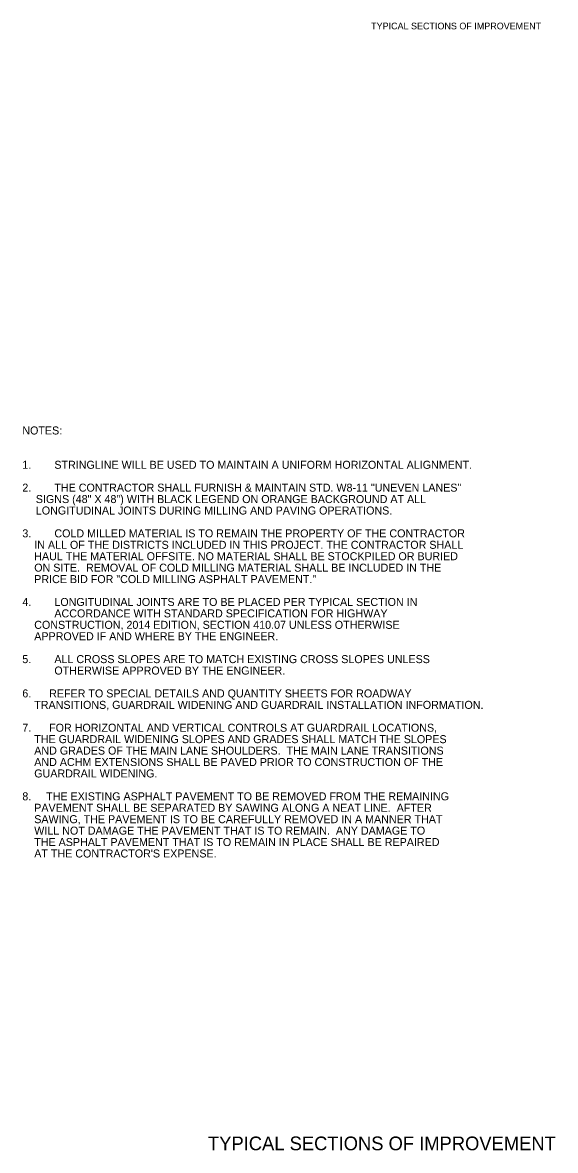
# Model space of a CAD drawing. Extents: x 544259 to 1930787, y -1961343 to 596640.
# Drawn here: x 545302 to 545768, y -1949643 to -1948656 of the extents above; entities that cross this region are included whole.
import ezdxf

# ---------------------------------------------------------------- set-up
doc = ezdxf.new("R2010")
doc.units = 0
for name, color, linetype in [('R_Border', 7, 'Continuous'), ('R_Border Notes', 7, 'Continuous'), ('R_Border Prem', 7, 'Continuous')]:
    doc.layers.add(name, color=color, linetype=linetype)

msp = doc.modelspace()

# ---------------------------------------------------------------- texts
at = {"layer": 'R_Border'}
msp.add_text('TYPICAL SECTIONS OF IMPROVEMENT', height=12, rotation=360, dxfattribs=at).set_placement((545464.19, -1949642.82))
at = {"layer": 'R_Border Notes'}
for s, p in [('NOTES: ', (545301.92, -1949016.74)), ('1.', (545301.92, -1949046.74)), ('STRINGLINE WILL BE USED TO MAINTAIN A UNIFORM HORIZONTAL ALIGNMENT.', (545329.92, -1949046.74)), ('2.', (545301.92, -1949066.74)), ('THE CONTRACTOR SHALL FURNISH & MAINTAIN STD. W8-11 "UNEVEN LANES" ', (545329.92, -1949066.74)), ('    SIGNS (48" X 48") WITH BLACK LEGEND ON ORANGE BACKGROUND AT ALL ', (545303.32, -1949076.74)), ('    LONGITUDINAL JOINTS DURING MILLING AND PAVING OPERATIONS.', (545303.32, -1949086.74)), ('3.', (545301.92, -1949106.74)), ('COLD MILLED MATERIAL IS TO REMAIN THE PROPERTY OF THE CONTRACTOR', (545329.92, -1949106.74)), ('    IN ALL OF THE DISTRICTS INCLUDED IN THIS PROJECT. THE CONTRACTOR SHALL', (545301.92, -1949116.74)), ('    HAUL THE MATERIAL OFFSITE. NO MATERIAL SHALL BE STOCKPILED OR BURIED', (545301.92, -1949126.74)), ('    ON SITE.  REMOVAL OF COLD MILLING MATERIAL SHALL BE INCLUDED IN THE', (545301.92, -1949136.74)), ('    PRICE BID FOR "COLD MILLING ASPHALT PAVEMENT."', (545301.92, -1949146.74)), ('4.', (545301.92, -1949166.74)), ('LONGITUDINAL JOINTS ARE TO BE PLACED PER TYPICAL SECTION IN ', (545329.92, -1949166.74)), ('ACCORDANCE WITH STANDARD SPECIFICATION FOR HIGHWAY', (545329.92, -1949176.74)), ('    CONSTRUCTION, 2014 EDITION, SECTION 410.07 UNLESS OTHERWISE', (545301.92, -1949186.74)), ('    APPROVED IF AND WHERE BY THE ENGINEER.', (545301.92, -1949196.74)), ('5.', (545301.92, -1949216.74)), ('ALL CROSS SLOPES ARE TO MATCH EXISTING CROSS SLOPES UNLESS ', (545329.92, -1949216.74)), ('OTHERWISE APPROVED BY THE ENGINEER.', (545329.92, -1949226.74)), ('6.      REFER TO SPECIAL DETAILS AND QUANTITY SHEETS FOR ROADWAY', (545301.92, -1949246.74)), ('    TRANSITIONS, GUARDRAIL WIDENING AND GUARDRAIL INSTALLATION INFORMATION.', (545301.92, -1949256.74)), ('7.      FOR HORIZONTAL AND VERTICAL CONTROLS AT GUARDRAIL LOCATIONS,', (545301.92, -1949276.74)), ('    THE GUARDRAIL WIDENING SLOPES AND GRADES SHALL MATCH THE SLOPES', (545301.92, -1949286.74)), ('    AND GRADES OF THE MAIN LANE SHOULDERS.  THE MAIN LANE TRANSITIONS', (545301.92, -1949296.74)), ('    AND ACHM EXTENSIONS SHALL BE PAVED PRIOR TO CONSTRUCTION OF THE', (545301.92, -1949306.74)), ('    GUARDRAIL WIDENING.', (545301.92, -1949316.74)), ('8.     THE EXISTING ASPHALT PAVEMENT TO BE REMOVED FROM THE REMAINING', (545301.92, -1949336.74)), ('    PAVEMENT SHALL BE SEPARATED BY SAWING ALONG A NEAT LINE.  AFTER', (545301.92, -1949346.74)), ('    SAWING, THE PAVEMENT IS TO BE CAREFULLY REMOVED IN A MANNER THAT ', (545301.92, -1949356.74)), ('    WILL NOT DAMAGE THE PAVEMENT THAT IS TO REMAIN.  ANY DAMAGE TO', (545301.92, -1949366.74)), ('    THE ASPHALT PAVEMENT THAT IS TO REMAIN IN PLACE SHALL BE REPAIRED', (545301.92, -1949376.74)), ("    AT THE CONTRACTOR'S EXPENSE.", (545301.92, -1949386.74))]:
    msp.add_text(s, height=7, dxfattribs=at).set_placement(p)
at = {"layer": 'R_Border Prem'}
msp.add_text('TYPICAL SECTIONS OF IMPROVEMENT', height=5.862, rotation=360, dxfattribs=at).set_placement((545606.81, -1948662.39))

doc.saveas('drawing.dxf')
